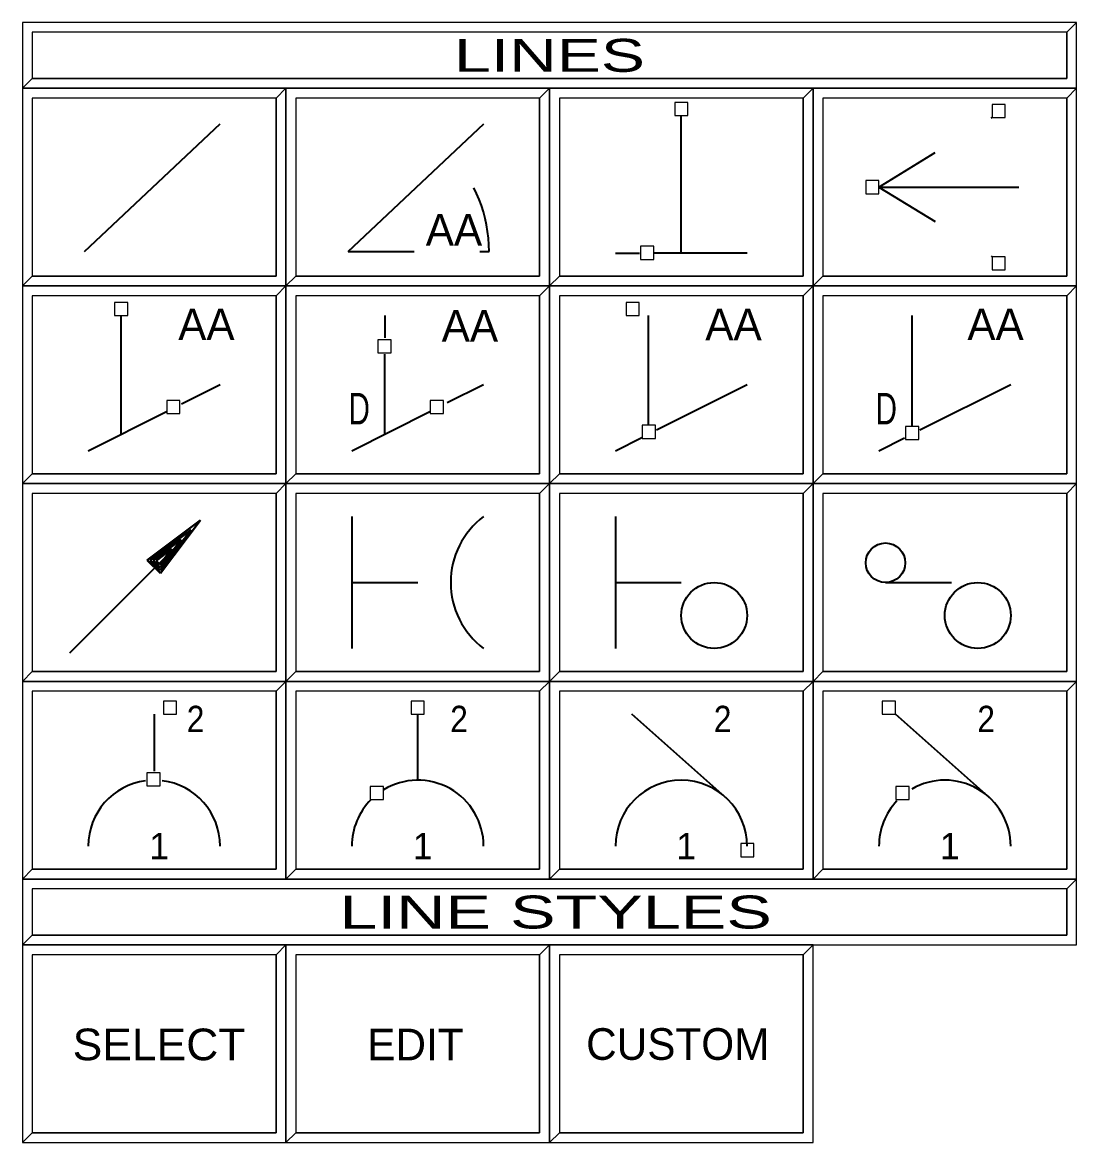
# Model space of a CAD drawing. Extents: x 95906.8 to 95923.6, y 90964.8 to 90972.8.
# Drawn here: x 95908.935 to 95910.535, y 90967.889 to 90969.589 of the extents above; entities that cross this region are included whole.
import ezdxf
from ezdxf.enums import TextEntityAlignment as Align

# ---------------------------------------------------------------- set-up
doc = ezdxf.new("R2010")
doc.units = 0
doc.header["$LTSCALE"] = 0.019
doc.linetypes.add('MEDIUM_DASHED', pattern=[4.5, 3, -1.5])
for name, color, linetype, lineweight in [('1', 7, 'Continuous', 25), ('11', 7, 'Continuous', 25), ('12', 7, 'Continuous', 25), ('17', 7, 'Continuous', 25), ('2', 7, 'Continuous', 13), ('21', 7, 'Continuous', 25), ('3', 7, 'Continuous', 25), ('6', 7, 'Continuous', 35), ('7', 7, 'Continuous', 35)]:
    doc.layers.add(name, color=color, linetype=linetype, lineweight=lineweight)

msp = doc.modelspace()

# ---------------------------------------------------------------- linework, layer by layer
at = {"layer": '1'}
for points in [[(95908.9346, 90969.4887), (95910.5346, 90969.4887), (95910.5346, 90969.5887), (95908.9346, 90969.5887)], [(95908.9346, 90969.1887), (95909.3346, 90969.1887), (95909.3346, 90969.4887), (95908.9346, 90969.4887)], [(95909.3346, 90969.1887), (95909.7346, 90969.1887), (95909.7346, 90969.4887), (95909.3346, 90969.4887)], [(95909.7346, 90969.1887), (95910.1346, 90969.1887), (95910.1346, 90969.4887), (95909.7346, 90969.4887)], [(95910.1346, 90969.1887), (95910.5346, 90969.1887), (95910.5346, 90969.4887), (95910.1346, 90969.4887)], [(95908.9346, 90968.8887), (95909.3346, 90968.8887), (95909.3346, 90969.1887), (95908.9346, 90969.1887)], [(95909.3346, 90968.8887), (95909.7346, 90968.8887), (95909.7346, 90969.1887), (95909.3346, 90969.1887)], [(95909.7346, 90968.8887), (95910.1346, 90968.8887), (95910.1346, 90969.1887), (95909.7346, 90969.1887)], [(95910.1346, 90968.8887), (95910.5346, 90968.8887), (95910.5346, 90969.1887), (95910.1346, 90969.1887)], [(95908.9346, 90968.5887), (95909.3346, 90968.5887), (95909.3346, 90968.8887), (95908.9346, 90968.8887)], [(95909.3346, 90968.5887), (95909.7346, 90968.5887), (95909.7346, 90968.8887), (95909.3346, 90968.8887)], [(95909.7346, 90968.5887), (95910.1346, 90968.5887), (95910.1346, 90968.8887), (95909.7346, 90968.8887)], [(95910.1346, 90968.5887), (95910.5346, 90968.5887), (95910.5346, 90968.8887), (95910.1346, 90968.8887)], [(95908.9346, 90968.2887), (95909.3346, 90968.2887), (95909.3346, 90968.5887), (95908.9346, 90968.5887)], [(95909.3346, 90968.2887), (95909.7346, 90968.2887), (95909.7346, 90968.5887), (95909.3346, 90968.5887)], [(95909.7346, 90968.2887), (95910.1346, 90968.2887), (95910.1346, 90968.5887), (95909.7346, 90968.5887)], [(95910.1346, 90968.2887), (95910.5346, 90968.2887), (95910.5346, 90968.5887), (95910.1346, 90968.5887)], [(95908.9346, 90968.1887), (95910.5346, 90968.1887), (95910.5346, 90968.2887), (95908.9346, 90968.2887)], [(95908.9346, 90967.8887), (95909.3346, 90967.8887), (95909.3346, 90968.1887), (95908.9346, 90968.1887)], [(95909.3346, 90967.8887), (95909.7346, 90967.8887), (95909.7346, 90968.1887), (95909.3346, 90968.1887)], [(95909.7346, 90967.8887), (95910.1346, 90967.8887), (95910.1346, 90968.1887), (95909.7346, 90968.1887)]]:
    msp.add_lwpolyline(points, close=True, dxfattribs=at)
at = {"layer": '11'}
for points in [[(95909.3496, 90969.2037), (95909.7196, 90969.2037), (95909.7196, 90969.4737), (95909.3496, 90969.4737)], [(95909.7496, 90969.2037), (95910.1196, 90969.2037), (95910.1196, 90969.4737), (95909.7496, 90969.4737)], [(95910.1496, 90969.2037), (95910.5196, 90969.2037), (95910.5196, 90969.4737), (95910.1496, 90969.4737)], [(95908.9496, 90968.9037), (95909.3196, 90968.9037), (95909.3196, 90969.1737), (95908.9496, 90969.1737)], [(95909.3496, 90968.9037), (95909.7196, 90968.9037), (95909.7196, 90969.1737), (95909.3496, 90969.1737)], [(95909.7496, 90968.9037), (95910.1196, 90968.9037), (95910.1196, 90969.1737), (95909.7496, 90969.1737)], [(95910.1496, 90968.9037), (95910.5196, 90968.9037), (95910.5196, 90969.1737), (95910.1496, 90969.1737)], [(95908.9496, 90968.6037), (95909.3196, 90968.6037), (95909.3196, 90968.8737), (95908.9496, 90968.8737)], [(95909.3496, 90968.6037), (95909.7196, 90968.6037), (95909.7196, 90968.8737), (95909.3496, 90968.8737)], [(95909.7496, 90968.6037), (95910.1196, 90968.6037), (95910.1196, 90968.8737), (95909.7496, 90968.8737)], [(95910.1496, 90968.6037), (95910.5196, 90968.6037), (95910.5196, 90968.8737), (95910.1496, 90968.8737)], [(95908.9496, 90968.3037), (95909.3196, 90968.3037), (95909.3196, 90968.5737), (95908.9496, 90968.5737)], [(95909.3496, 90968.3037), (95909.7196, 90968.3037), (95909.7196, 90968.5737), (95909.3496, 90968.5737)], [(95909.7496, 90968.3037), (95910.1196, 90968.3037), (95910.1196, 90968.5737), (95909.7496, 90968.5737)], [(95910.1496, 90968.3037), (95910.5196, 90968.3037), (95910.5196, 90968.5737), (95910.1496, 90968.5737)], [(95908.9496, 90967.9037), (95909.3196, 90967.9037), (95909.3196, 90968.1737), (95908.9496, 90968.1737)], [(95909.3496, 90967.9037), (95909.7196, 90967.9037), (95909.7196, 90968.1737), (95909.3496, 90968.1737)], [(95909.7496, 90967.9037), (95910.1196, 90967.9037), (95910.1196, 90968.1737), (95909.7496, 90968.1737)]]:
    msp.add_lwpolyline(points, close=True, dxfattribs=at)
at = {"layer": '12'}
msp.add_lwpolyline([(95908.9496, 90969.2037), (95909.3196, 90969.2037), (95909.3196, 90969.4737), (95908.9496, 90969.4737)], close=True, dxfattribs=at)
at = {"layer": '17'}
msp.add_lwpolyline([(95908.9496, 90969.5037), (95910.5196, 90969.5037), (95910.5196, 90969.5737), (95908.9496, 90969.5737)], close=True, dxfattribs=at)
at = {"layer": '2'}
for points in [[(95908.9346, 90969.5887), (95908.9346, 90969.4887), (95908.9496, 90969.5037), (95908.9496, 90969.5737), (95910.5196, 90969.5737), (95910.5346, 90969.5887)], [(95908.9346, 90969.4887), (95908.9346, 90969.1887), (95908.9496, 90969.2037), (95908.9496, 90969.4737), (95909.3196, 90969.4737), (95909.3346, 90969.4887)], [(95909.3346, 90969.4887), (95909.3346, 90969.1887), (95909.3496, 90969.2037), (95909.3496, 90969.4737), (95909.7196, 90969.4737), (95909.7346, 90969.4887)], [(95909.7346, 90969.4887), (95909.7346, 90969.1887), (95909.7496, 90969.2037), (95909.7496, 90969.4737), (95910.1196, 90969.4737), (95910.1346, 90969.4887)], [(95910.1346, 90969.4887), (95910.1346, 90969.1887), (95910.1496, 90969.2037), (95910.1496, 90969.4737), (95910.5196, 90969.4737), (95910.5346, 90969.4887)], [(95908.9346, 90969.1887), (95908.9346, 90968.8887), (95908.9496, 90968.9037), (95908.9496, 90969.1737), (95909.3196, 90969.1737), (95909.3346, 90969.1887)], [(95909.3346, 90969.1887), (95909.3346, 90968.8887), (95909.3496, 90968.9037), (95909.3496, 90969.1737), (95909.7196, 90969.1737), (95909.7346, 90969.1887)], [(95909.7346, 90969.1887), (95909.7346, 90968.8887), (95909.7496, 90968.9037), (95909.7496, 90969.1737), (95910.1196, 90969.1737), (95910.1346, 90969.1887)], [(95910.1346, 90969.1887), (95910.1346, 90968.8887), (95910.1496, 90968.9037), (95910.1496, 90969.1737), (95910.5196, 90969.1737), (95910.5346, 90969.1887)], [(95908.9346, 90968.8887), (95908.9346, 90968.5887), (95908.9496, 90968.6037), (95908.9496, 90968.8737), (95909.3196, 90968.8737), (95909.3346, 90968.8887)], [(95909.3346, 90968.8887), (95909.3346, 90968.5887), (95909.3496, 90968.6037), (95909.3496, 90968.8737), (95909.7196, 90968.8737), (95909.7346, 90968.8887)], [(95909.7346, 90968.8887), (95909.7346, 90968.5887), (95909.7496, 90968.6037), (95909.7496, 90968.8737), (95910.1196, 90968.8737), (95910.1346, 90968.8887)], [(95910.1346, 90968.8887), (95910.1346, 90968.5887), (95910.1496, 90968.6037), (95910.1496, 90968.8737), (95910.5196, 90968.8737), (95910.5346, 90968.8887)], [(95908.9346, 90968.5887), (95908.9346, 90968.2887), (95908.9496, 90968.3037), (95908.9496, 90968.5737), (95909.3196, 90968.5737), (95909.3346, 90968.5887)], [(95909.3346, 90968.5887), (95909.3346, 90968.2887), (95909.3496, 90968.3037), (95909.3496, 90968.5737), (95909.7196, 90968.5737), (95909.7346, 90968.5887)], [(95909.7346, 90968.5887), (95909.7346, 90968.2887), (95909.7496, 90968.3037), (95909.7496, 90968.5737), (95910.1196, 90968.5737), (95910.1346, 90968.5887)], [(95910.1346, 90968.5887), (95910.1346, 90968.2887), (95910.1496, 90968.3037), (95910.1496, 90968.5737), (95910.5196, 90968.5737), (95910.5346, 90968.5887)], [(95908.9346, 90968.2887), (95908.9346, 90968.1887), (95908.9496, 90968.2037), (95908.9496, 90968.2737), (95910.5196, 90968.2737), (95910.5346, 90968.2887)], [(95908.9346, 90968.1887), (95908.9346, 90967.8887), (95908.9496, 90967.9037), (95908.9496, 90968.1737), (95909.3196, 90968.1737), (95909.3346, 90968.1887)], [(95909.3346, 90968.1887), (95909.3346, 90967.8887), (95909.3496, 90967.9037), (95909.3496, 90968.1737), (95909.7196, 90968.1737), (95909.7346, 90968.1887)], [(95909.7346, 90968.1887), (95909.7346, 90967.8887), (95909.7496, 90967.9037), (95909.7496, 90968.1737), (95910.1196, 90968.1737), (95910.1346, 90968.1887)], [(95909.7346, 90968.1887), (95909.7346, 90967.8887), (95909.7496, 90967.9037), (95909.7496, 90968.1737), (95910.1196, 90968.1737), (95910.1346, 90968.1887)]]:
    msp.add_lwpolyline(points, close=True, dxfattribs=at)
at = {"layer": '21'}
msp.add_lwpolyline([(95908.9496, 90968.2037), (95910.5196, 90968.2037), (95910.5196, 90968.2737), (95908.9496, 90968.2737)], close=True, dxfattribs=at)
at = {"layer": '3'}
for points in [[(95908.9346, 90969.4887), (95910.5346, 90969.4887), (95910.5346, 90969.5887), (95910.5196, 90969.5737), (95910.5196, 90969.5037), (95908.9496, 90969.5037)], [(95908.9346, 90969.1887), (95909.3346, 90969.1887), (95909.3346, 90969.4887), (95909.3196, 90969.4737), (95909.3196, 90969.2037), (95908.9496, 90969.2037)], [(95909.3346, 90969.1887), (95909.7346, 90969.1887), (95909.7346, 90969.4887), (95909.7196, 90969.4737), (95909.7196, 90969.2037), (95909.3496, 90969.2037)], [(95909.7346, 90969.1887), (95910.1346, 90969.1887), (95910.1346, 90969.4887), (95910.1196, 90969.4737), (95910.1196, 90969.2037), (95909.7496, 90969.2037)], [(95910.1346, 90969.1887), (95910.5346, 90969.1887), (95910.5346, 90969.4887), (95910.5196, 90969.4737), (95910.5196, 90969.2037), (95910.1496, 90969.2037)], [(95908.9346, 90968.8887), (95909.3346, 90968.8887), (95909.3346, 90969.1887), (95909.3196, 90969.1737), (95909.3196, 90968.9037), (95908.9496, 90968.9037)], [(95909.3346, 90968.8887), (95909.7346, 90968.8887), (95909.7346, 90969.1887), (95909.7196, 90969.1737), (95909.7196, 90968.9037), (95909.3496, 90968.9037)], [(95909.7346, 90968.8887), (95910.1346, 90968.8887), (95910.1346, 90969.1887), (95910.1196, 90969.1737), (95910.1196, 90968.9037), (95909.7496, 90968.9037)], [(95910.1346, 90968.8887), (95910.5346, 90968.8887), (95910.5346, 90969.1887), (95910.5196, 90969.1737), (95910.5196, 90968.9037), (95910.1496, 90968.9037)], [(95908.9346, 90968.5887), (95909.3346, 90968.5887), (95909.3346, 90968.8887), (95909.3196, 90968.8737), (95909.3196, 90968.6037), (95908.9496, 90968.6037)], [(95909.3346, 90968.5887), (95909.7346, 90968.5887), (95909.7346, 90968.8887), (95909.7196, 90968.8737), (95909.7196, 90968.6037), (95909.3496, 90968.6037)], [(95909.7346, 90968.5887), (95910.1346, 90968.5887), (95910.1346, 90968.8887), (95910.1196, 90968.8737), (95910.1196, 90968.6037), (95909.7496, 90968.6037)], [(95910.1346, 90968.5887), (95910.5346, 90968.5887), (95910.5346, 90968.8887), (95910.5196, 90968.8737), (95910.5196, 90968.6037), (95910.1496, 90968.6037)], [(95908.9346, 90968.2887), (95909.3346, 90968.2887), (95909.3346, 90968.5887), (95909.3196, 90968.5737), (95909.3196, 90968.3037), (95908.9496, 90968.3037)], [(95909.3346, 90968.2887), (95909.7346, 90968.2887), (95909.7346, 90968.5887), (95909.7196, 90968.5737), (95909.7196, 90968.3037), (95909.3496, 90968.3037)], [(95909.7346, 90968.2887), (95910.1346, 90968.2887), (95910.1346, 90968.5887), (95910.1196, 90968.5737), (95910.1196, 90968.3037), (95909.7496, 90968.3037)], [(95910.1346, 90968.2887), (95910.5346, 90968.2887), (95910.5346, 90968.5887), (95910.5196, 90968.5737), (95910.5196, 90968.3037), (95910.1496, 90968.3037)], [(95908.9346, 90968.1887), (95910.5346, 90968.1887), (95910.5346, 90968.2887), (95910.5196, 90968.2737), (95910.5196, 90968.2037), (95908.9496, 90968.2037)], [(95908.9346, 90967.8887), (95909.3346, 90967.8887), (95909.3346, 90968.1887), (95909.3196, 90968.1737), (95909.3196, 90967.9037), (95908.9496, 90967.9037)], [(95909.3346, 90967.8887), (95909.7346, 90967.8887), (95909.7346, 90968.1887), (95909.7196, 90968.1737), (95909.7196, 90967.9037), (95909.3496, 90967.9037)], [(95909.7346, 90967.8887), (95910.1346, 90967.8887), (95910.1346, 90968.1887), (95910.1196, 90968.1737), (95910.1196, 90967.9037), (95909.7496, 90967.9037)]]:
    msp.add_lwpolyline(points, close=True, dxfattribs=at)
at = {"layer": '6'}
for p, q in [((95909.029, 90969.2412), (95909.235, 90969.435)), ((95909.429, 90969.2412), (95909.635, 90969.435)), ((95909.9346, 90969.2387), (95909.9346, 90969.4472)), ((95910.2346, 90969.3387), (95910.4467, 90969.3387)), ((95909.8346, 90969.2387), (95909.871, 90969.2387)), ((95910.0346, 90969.2387), (95909.8929, 90969.2387)), ((95909.0846, 90968.9637), (95909.0846, 90969.1437)), ((95909.4846, 90969.1437), (95909.4846, 90969.1098)), ((95909.8846, 90969.1437), (95909.8846, 90968.9781)), ((95910.2846, 90969.1437), (95910.2846, 90968.9755)), ((95909.4846, 90968.9637), (95909.4846, 90969.0853)), ((95909.2346, 90969.0387), (95909.176, 90969.0094)), ((95909.6346, 90969.0387), (95909.5795, 90969.0112)), ((95910.0346, 90969.0387), (95909.8969, 90968.9699)), ((95910.4346, 90969.0387), (95910.2969, 90968.9698)), ((95909.0346, 90968.9387), (95909.1534, 90968.9981)), ((95909.4346, 90968.9387), (95909.5532, 90968.998)), ((95909.8346, 90968.9387), (95909.8747, 90968.9588)), ((95910.2346, 90968.9387), (95910.2736, 90968.9582)), ((95909.4346, 90968.8387), (95909.4346, 90968.6387)), ((95909.8346, 90968.8387), (95909.8346, 90968.6387)), ((95909.1639, 90968.7895), (95909.0059, 90968.6315)), ((95909.1346, 90968.5387), (95909.1346, 90968.4525)), ((95909.5346, 90968.4387), (95909.5346, 90968.5387)), ((95910.0053, 90968.4094), (95909.8596, 90968.5387)), ((95910.4053, 90968.4094), (95910.2596, 90968.5387))]:
    msp.add_line(p, q, dxfattribs=at)
at = {"layer": '6', "linetype": 'MEDIUM_DASHED'}
for p, q in [((95910.2346, 90969.3387), (95910.4063, 90969.4443)), ((95910.2346, 90969.3387), (95910.4063, 90969.2331)), ((95909.429, 90969.2412), (95909.6429, 90969.2412)), ((95909.4346, 90968.7387), (95909.5846, 90968.7387)), ((95909.8346, 90968.7387), (95909.9846, 90968.7387)), ((95910.2446, 90968.7387), (95910.3846, 90968.7387))]:
    msp.add_line(p, q, dxfattribs=at)
at = {"layer": '6', "lineweight": 40}
for p, q in [((95909.205, 90968.8333), (95909.1242, 90968.7727)), ((95909.205, 90968.8333), (95909.1441, 90968.7528)), ((95909.1905, 90968.8188), (95909.1285, 90968.7724)), ((95909.1758, 90968.8042), (95909.133, 90968.7721)), ((95909.1758, 90968.8042), (95909.1435, 90968.7616)), ((95909.1905, 90968.8188), (95909.1438, 90968.7573)), ((95909.1612, 90968.7897), (95909.1374, 90968.7718)), ((95909.1612, 90968.7897), (95909.1432, 90968.766)), ((95909.1441, 90968.7528), (95909.1242, 90968.7727)), ((95909.1438, 90968.7573), (95909.1285, 90968.7724)), ((95909.1435, 90968.7616), (95909.133, 90968.7721)), ((95909.1432, 90968.766), (95909.1374, 90968.7718))]:
    msp.add_line(p, q, dxfattribs=at)
at = {"layer": '6', "lineweight": 25}
for points in [[(95909.9246, 90969.4472), (95909.9446, 90969.4472), (95909.9446, 90969.4672), (95909.9246, 90969.4672)], [(95910.4063, 90969.4443), (95910.4263, 90969.4443), (95910.4263, 90969.4643), (95910.4063, 90969.4643)], [(95910.2146, 90969.3287), (95910.2346, 90969.3287), (95910.2346, 90969.3487), (95910.2146, 90969.3487)], [(95909.8729, 90969.2289), (95909.8929, 90969.2289), (95909.8929, 90969.2489), (95909.8729, 90969.2489)], [(95910.4063, 90969.2131), (95910.4263, 90969.2131), (95910.4263, 90969.2331), (95910.4063, 90969.2331)], [(95909.0746, 90969.1437), (95909.0946, 90969.1437), (95909.0946, 90969.1637), (95909.0746, 90969.1637)], [(95909.8509, 90969.1437), (95909.8709, 90969.1437), (95909.8709, 90969.1637), (95909.8509, 90969.1637)], [(95909.4743, 90969.0872), (95909.4943, 90969.0872), (95909.4943, 90969.1072), (95909.4743, 90969.1072)], [(95909.1536, 90968.995), (95909.1736, 90968.995), (95909.1736, 90969.015), (95909.1536, 90969.015)], [(95909.5536, 90968.995), (95909.5736, 90968.995), (95909.5736, 90969.015), (95909.5536, 90969.015)], [(95909.8754, 90968.9574), (95909.8954, 90968.9574), (95909.8954, 90968.9774), (95909.8754, 90968.9774)], [(95910.275, 90968.9555), (95910.295, 90968.9555), (95910.295, 90968.9755), (95910.275, 90968.9755)], [(95909.1486, 90968.5387), (95909.1686, 90968.5387), (95909.1686, 90968.5587), (95909.1486, 90968.5587)], [(95909.5246, 90968.5387), (95909.5446, 90968.5387), (95909.5446, 90968.5587), (95909.5246, 90968.5587)], [(95910.2396, 90968.5387), (95910.2596, 90968.5387), (95910.2596, 90968.5587), (95910.2396, 90968.5587)], [(95909.1236, 90968.4299), (95909.1436, 90968.4299), (95909.1436, 90968.4499), (95909.1236, 90968.4499)], [(95909.4625, 90968.4092), (95909.4825, 90968.4092), (95909.4825, 90968.4292), (95909.4625, 90968.4292)], [(95910.2604, 90968.4092), (95910.2804, 90968.4092), (95910.2804, 90968.4292), (95910.2604, 90968.4292)], [(95910.0249, 90968.3226), (95910.0449, 90968.3226), (95910.0449, 90968.3426), (95910.0249, 90968.3426)]]:
    msp.add_lwpolyline(points, close=True, dxfattribs=at)
at = {"layer": '6'}
for centre, radius in [((95910.2446, 90968.7687), 0.03), ((95909.9846, 90968.6887), 0.05), ((95910.3846, 90968.6887), 0.05)]:
    msp.add_circle(centre, radius, dxfattribs=at)
at = {"layer": '6', "linetype": 'MEDIUM_DASHED'}
msp.add_arc((95909.429, 90969.2412), 0.2139, 0, 43.2522, dxfattribs=at)
at = {"layer": '6'}
for centre, radius, start, end in [((95909.7096, 90968.7387), 0.125, 126.8699, 233.1301), ((95909.1346, 90968.3387), 0.1, 97.558, 180), ((95909.1346, 90968.3387), 0.1, 0, 82.9369), ((95909.5346, 90968.3387), 0.1, 0, 121.3266), ((95909.9346, 90968.3387), 0.1, 0, 180), ((95910.3346, 90968.3387), 0.1, 0, 119.9911), ((95909.5346, 90968.3387), 0.1, 135.1578, 180), ((95910.3346, 90968.3387), 0.1, 136.7381, 180)]:
    msp.add_arc(centre, radius, start, end, dxfattribs=at)

# ---------------------------------------------------------------- texts
for s, height, p in [('AA', 0.048, (95909.5896, 90969.2499)), ('AA', 0.048, (95909.2139, 90969.1065)), ('AA', 0.048, (95909.6138, 90969.1043)), ('AA', 0.048, (95910.0139, 90969.1064)), ('AA', 0.048, (95910.4116, 90969.1065)), ('1', 0.04, (95909.1421, 90968.3187)), ('1', 0.04, (95909.5421, 90968.3187)), ('1', 0.04, (95909.9421, 90968.3187)), ('1', 0.04, (95910.3421, 90968.3187)), ('EDIT', 0.048, (95909.5311, 90968.0136)), ('CUSTOM', 0.048, (95909.9293, 90968.0143))]:
    msp.add_text(s, height=height, dxfattribs=at).set_placement(p, align=Align.CENTER)
for s, height, width, p in [('D', 0.048, 0.7, (95909.4458, 90968.9785)), ('D', 0.048, 0.7, (95910.2458, 90968.9785)), ('2', 0.04, 0.9, (95909.1974, 90968.5116)), ('2', 0.04, 0.9, (95909.5973, 90968.5116)), ('2', 0.04, 0.9, (95909.9974, 90968.5116)), ('2', 0.04, 0.9, (95910.3973, 90968.5116)), ('SELECT', 0.048, 1.05, (95909.142, 90968.0137))]:
    msp.add_text(s, height=height, dxfattribs=dict(at, width=width)).set_placement(p, align=Align.CENTER)
at = {"layer": '7'}
for s, height, width, p in [('         LINES         ', 0.04999, 1.5, (95909.7346, 90969.5137)), ('    LINE STYLES    ', 0.05, 1.55, (95909.7438, 90968.2136))]:
    msp.add_text(s, height=height, dxfattribs=dict(at, width=width)).set_placement(p, align=Align.CENTER)

doc.saveas('drawing.dxf')
